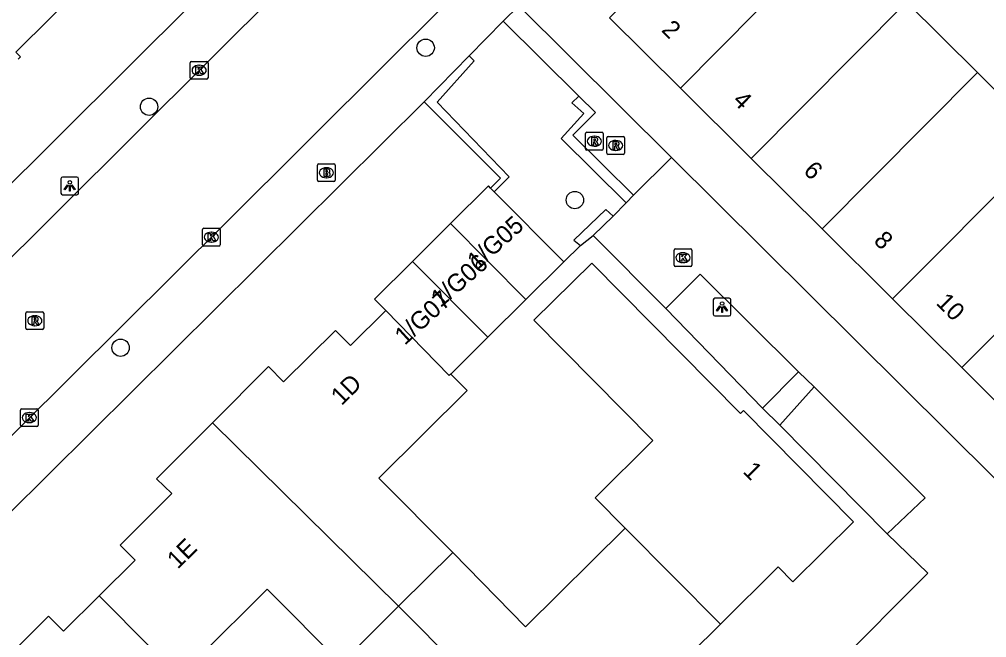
# Model space of a CAD drawing. Extents: x 159222 to 160346, y 381249 to 382166.
# Drawn here: x 160085.3 to 160139.8, y 381846.3 to 381881.1 of the extents above; entities that cross this region are included whole.
import ezdxf

# ---------------------------------------------------------------- set-up
doc = ezdxf.new("R2010")
doc.units = 0
for name, color, linetype in [('IMGEO_Boom', 7, 'Continuous'), ('IMGEO_Brandkraan', 7, 'Continuous'), ('IMGEO_Groenvoorziening', 7, 'Continuous'), ('IMGEO_Haag', 7, 'Continuous'), ('IMGEO_Kolk', 7, 'Continuous'), ('IMGEO_Lichtpunt', 7, 'Continuous'), ('IMGEO_Pand', 7, 'Continuous'), ('IMGEO_Pand_nummerreeks', 7, 'Continuous'), ('IMGEO_Rijbaan_lokaal_open', 7, 'Continuous'), ('IMGEO_Rioolput', 7, 'Continuous'), ('IMGEO_Voetpad_open', 7, 'Continuous')]:
    doc.layers.add(name, color=color, linetype=linetype)

msp = doc.modelspace()

# ---------------------------------------------------------------- linework, layer by layer
at = {"layer": 'IMGEO_Boom'}
for centre in [(160108.207, 381879.53), (160092.632, 381876.209), (160116.609, 381870.954), (160091.023, 381862.638)]:
    msp.add_circle(centre, 0.489, dxfattribs=at)
at = {"layer": 'IMGEO_Brandkraan'}
for p, q in [((160102.192, 381872.993), (160103.044, 381872.993)), ((160102.117, 381872.067), (160102.117, 381872.919)), ((160102.605, 381872.773), (160102.63, 381872.773)), ((160103.118, 381872.919), (160103.118, 381872.067)), ((160103.044, 381871.993), (160102.192, 381871.993)), ((160102.628, 381872.213), (160102.603, 381872.213))]:
    msp.add_line(p, q, dxfattribs=at)
for points in [[(160102.192, 381872.993), (160103.044, 381872.993)], [(160102.117, 381872.067), (160102.117, 381872.919)], [(160102.465, 381872.693), (160102.465, 381872.293), (160102.678, 381872.293)], [(160102.696, 381872.693), (160102.465, 381872.693)], [(160102.644, 381872.612), (160102.59, 381872.612), (160102.59, 381872.536)], [(160102.59, 381872.536), (160102.643, 381872.536)], [(160102.652, 381872.46), (160102.59, 381872.46), (160102.59, 381872.379)], [(160103.118, 381872.919), (160103.118, 381872.067)], [(160103.044, 381871.993), (160102.192, 381871.993)], [(160102.59, 381872.379), (160102.652, 381872.379)]]:
    msp.add_lwpolyline(points, dxfattribs=at)
for centre, radius, start, end in [((160102.194, 381872.917), 0.0765, 91.552, 178.448), ((160102.194, 381872.917), 0.0765, 91.552, 178.448), ((160103.042, 381872.917), 0.0765, 1.552, 88.448), ((160103.042, 381872.917), 0.0765, 1.552, 88.448), ((160102.645, 381872.574), 0.0379, 267.8285, 90.9355), ((160102.653, 381872.419), 0.0404, 269.8759, 90.5077), ((160102.7, 381872.548), 0.145, 59.4692, 91.5367), ((160102.725, 381872.595), 0.0922, 285.5137, 58.1501), ((160102.73, 381872.403), 0.105, 301.3115, 78.989), ((160102.194, 381872.069), 0.0765, 181.552, 268.448), ((160102.194, 381872.069), 0.0765, 181.552, 268.448), ((160102.684, 381872.544), 0.251, 268.6676, 293.5347), ((160103.042, 381872.069), 0.0765, 271.552, 358.448), ((160103.042, 381872.069), 0.0765, 271.552, 358.448)]:
    msp.add_arc(centre, radius, start, end, dxfattribs=at)
for centre, major_axis, ratio, start_param, end_param in [((160102.604, 381872.493), (-0.387, 0.002), 0.722429, 4.712389, 7.853982), ((160102.629, 381872.493), (-0.39, 0.002), 0.717154, 1.570796, 4.712389)]:
    msp.add_ellipse(centre, major_axis=major_axis, ratio=ratio, start_param=start_param, end_param=end_param, dxfattribs=at)
at = {"layer": 'IMGEO_Groenvoorziening'}
for points in [[(160115.983, 381867.48), (160116.932, 381868.397)], [(160127.18, 381859.24), (160121.731, 381864.845)], [(160134.193, 381852.151), (160128.145, 381858.27)]]:
    msp.add_lwpolyline(points, dxfattribs=at)
at = {"layer": 'IMGEO_Haag'}
for points in [[(160112.065, 381871.426), (160112.908, 381872.255), (160108.851, 381876.475), (160110.94, 381878.792), (160110.658, 381879.072)], [(160116.824, 381876.807), (160116.445, 381876.433), (160117.122, 381875.832), (160115.838, 381874.429), (160119.501, 381870.804)], [(160108.118, 381876.482), (160112.429, 381872.19), (160111.865, 381871.628)], [(160118.769, 381870.052), (160118.356, 381870.426), (160116.554, 381868.698), (160116.932, 381868.397)], [(160116.932, 381868.397), (160117.637, 381868.956)]]:
    msp.add_lwpolyline(points, dxfattribs=at)
at = {"layer": 'IMGEO_Kolk'}
for p, q in [((160094.948, 381877.838), (160094.948, 381878.69)), ((160095.023, 381878.764), (160095.875, 381878.764)), ((160095.436, 381878.544), (160095.461, 381878.544)), ((160095.949, 381878.69), (160095.949, 381877.838)), ((160095.459, 381877.984), (160095.434, 381877.984)), ((160095.875, 381877.764), (160095.023, 381877.764)), ((160095.64, 381868.439), (160095.64, 381869.291)), ((160095.715, 381869.365), (160096.567, 381869.365)), ((160096.641, 381869.291), (160096.641, 381868.439)), ((160096.128, 381869.145), (160096.153, 381869.145)), ((160096.567, 381868.365), (160095.715, 381868.365)), ((160096.151, 381868.585), (160096.126, 381868.585)), ((160122.194, 381867.283), (160122.194, 381868.135)), ((160122.269, 381868.209), (160123.121, 381868.209)), ((160123.195, 381868.135), (160123.195, 381867.283)), ((160122.682, 381867.989), (160122.707, 381867.989)), ((160123.121, 381867.209), (160122.269, 381867.209)), ((160122.705, 381867.429), (160122.68, 381867.429)), ((160085.387, 381858.277), (160085.387, 381859.129)), ((160085.462, 381859.203), (160086.314, 381859.203)), ((160085.875, 381858.983), (160085.9, 381858.983)), ((160086.388, 381859.129), (160086.388, 381858.277)), ((160085.898, 381858.423), (160085.873, 381858.423)), ((160086.314, 381858.203), (160085.462, 381858.203))]:
    msp.add_line(p, q, dxfattribs=at)
for points in [[(160094.948, 381877.838), (160094.948, 381878.69)], [(160095.023, 381878.764), (160095.875, 381878.764)], [(160095.269, 381878.464), (160095.392, 381878.464), (160095.392, 381878.313), (160095.522, 381878.464), (160095.686, 381878.464), (160095.54, 381878.313), (160095.693, 381878.064), (160095.541, 381878.064), (160095.456, 381878.228), (160095.392, 381878.161), (160095.392, 381878.064), (160095.269, 381878.064), (160095.269, 381878.464)], [(160095.949, 381878.69), (160095.949, 381877.838)], [(160095.875, 381877.764), (160095.023, 381877.764)], [(160095.64, 381868.439), (160095.64, 381869.291)], [(160095.715, 381869.365), (160096.567, 381869.365)], [(160096.641, 381869.291), (160096.641, 381868.439)], [(160095.961, 381869.065), (160096.084, 381869.065), (160096.084, 381868.914), (160096.214, 381869.065), (160096.378, 381869.065), (160096.232, 381868.914), (160096.385, 381868.665), (160096.233, 381868.665), (160096.148, 381868.829), (160096.084, 381868.762), (160096.084, 381868.665), (160095.961, 381868.665), (160095.961, 381869.065)], [(160096.567, 381868.365), (160095.715, 381868.365)], [(160122.194, 381867.283), (160122.194, 381868.135)], [(160122.269, 381868.209), (160123.121, 381868.209)], [(160123.195, 381868.135), (160123.195, 381867.283)], [(160122.515, 381867.909), (160122.638, 381867.909), (160122.638, 381867.758), (160122.768, 381867.909), (160122.932, 381867.909), (160122.786, 381867.758), (160122.939, 381867.509), (160122.787, 381867.509), (160122.702, 381867.673), (160122.638, 381867.606), (160122.638, 381867.509), (160122.515, 381867.509), (160122.515, 381867.909)], [(160123.121, 381867.209), (160122.269, 381867.209)], [(160085.387, 381858.277), (160085.387, 381859.129)], [(160085.462, 381859.203), (160086.314, 381859.203)], [(160085.708, 381858.903), (160085.831, 381858.903), (160085.831, 381858.752), (160085.961, 381858.903), (160086.125, 381858.903), (160085.979, 381858.752), (160086.132, 381858.503), (160085.98, 381858.503), (160085.895, 381858.667), (160085.831, 381858.6), (160085.831, 381858.503), (160085.708, 381858.503), (160085.708, 381858.903)], [(160086.388, 381859.129), (160086.388, 381858.277)], [(160086.314, 381858.203), (160085.462, 381858.203)]]:
    msp.add_lwpolyline(points, dxfattribs=at)
for centre, start, end in [((160095.025, 381878.688), 91.552, 178.448), ((160095.025, 381878.688), 91.552, 178.448), ((160095.873, 381878.688), 1.552, 88.448), ((160095.873, 381878.688), 1.552, 88.448), ((160095.025, 381877.84), 181.552, 268.448), ((160095.025, 381877.84), 181.552, 268.448), ((160095.873, 381877.84), 271.552, 358.448), ((160095.873, 381877.84), 271.552, 358.448), ((160095.717, 381869.289), 91.552, 178.448), ((160095.717, 381869.289), 91.552, 178.448), ((160096.565, 381869.289), 1.552, 88.448), ((160096.565, 381869.289), 1.552, 88.448), ((160095.717, 381868.441), 181.552, 268.448), ((160095.717, 381868.441), 181.552, 268.448), ((160096.565, 381868.441), 271.552, 358.448), ((160096.565, 381868.441), 271.552, 358.448), ((160122.271, 381868.133), 91.552, 178.448), ((160122.271, 381868.133), 91.552, 178.448), ((160123.119, 381868.133), 1.552, 88.448), ((160123.119, 381868.133), 1.552, 88.448), ((160122.271, 381867.285), 181.552, 268.448), ((160122.271, 381867.285), 181.552, 268.448), ((160123.119, 381867.285), 271.552, 358.448), ((160123.119, 381867.285), 271.552, 358.448), ((160085.464, 381859.127), 91.552, 178.448), ((160085.464, 381859.127), 91.552, 178.448), ((160086.312, 381859.127), 1.552, 88.448), ((160086.312, 381859.127), 1.552, 88.448), ((160085.464, 381858.279), 181.552, 268.448), ((160085.464, 381858.279), 181.552, 268.448), ((160086.312, 381858.279), 271.552, 358.448), ((160086.312, 381858.279), 271.552, 358.448)]:
    msp.add_arc(centre, 0.0765, start, end, dxfattribs=at)
for centre, major_axis, ratio, start_param, end_param in [((160095.435, 381878.264), (-0.387, 0.002), 0.722429, 4.712389, 7.853982), ((160095.46, 381878.264), (-0.39, 0.002), 0.717154, 1.570796, 4.712389), ((160096.127, 381868.865), (-0.387, 0.002), 0.722429, 4.712389, 7.853982), ((160096.152, 381868.865), (-0.39, 0.002), 0.717154, 1.570796, 4.712389), ((160122.681, 381867.709), (-0.387, 0.002), 0.722429, 4.712389, 7.853982), ((160122.706, 381867.709), (-0.39, 0.002), 0.717154, 1.570796, 4.712389), ((160085.874, 381858.703), (-0.387, 0.002), 0.722429, 4.712389, 7.853982), ((160085.899, 381858.703), (-0.39, 0.002), 0.717154, 1.570796, 4.712389)]:
    msp.add_ellipse(centre, major_axis=major_axis, ratio=ratio, start_param=start_param, end_param=end_param, dxfattribs=at)
at = {"layer": 'IMGEO_Lichtpunt'}
for p, q in [((160087.665, 381872.157), (160087.665, 381871.35)), ((160087.665, 381872.157), (160087.665, 381871.35)), ((160088.567, 381872.252), (160087.759, 381872.252)), ((160088.567, 381872.252), (160087.759, 381872.252)), ((160088.661, 381871.35), (160088.661, 381872.157)), ((160088.661, 381871.35), (160088.661, 381872.157)), ((160087.759, 381871.256), (160088.567, 381871.256)), ((160087.759, 381871.256), (160088.567, 381871.256)), ((160125.304, 381865.423), (160124.496, 381865.423)), ((160125.304, 381865.423), (160124.496, 381865.423)), ((160124.402, 381865.328), (160124.402, 381864.521)), ((160124.402, 381865.328), (160124.402, 381864.521)), ((160125.398, 381864.521), (160125.398, 381865.328)), ((160125.398, 381864.521), (160125.398, 381865.328)), ((160124.496, 381864.427), (160125.304, 381864.427)), ((160124.496, 381864.427), (160125.304, 381864.427))]:
    msp.add_line(p, q, dxfattribs=at)
for points in [[(160088.039, 381871.821), (160088.078, 381871.793), (160087.89, 381871.531), (160087.852, 381871.558), (160088.039, 381871.821)], [(160088.141, 381871.773), (160088.188, 381871.773), (160088.188, 381871.451), (160088.141, 381871.451), (160088.141, 381871.773)], [(160088.251, 381871.793), (160088.289, 381871.82), (160088.476, 381871.558), (160088.437, 381871.53), (160088.251, 381871.793)], [(160124.776, 381864.992), (160124.815, 381864.964), (160124.627, 381864.702), (160124.589, 381864.729), (160124.776, 381864.992)], [(160124.878, 381864.944), (160124.925, 381864.944), (160124.925, 381864.622), (160124.878, 381864.622), (160124.878, 381864.944)], [(160124.988, 381864.964), (160125.026, 381864.991), (160125.213, 381864.729), (160125.174, 381864.701), (160124.988, 381864.964)]]:
    msp.add_lwpolyline(points, dxfattribs=at)
for centre in [(160088.164, 381871.955), (160124.901, 381865.126)]:
    msp.add_circle(centre, 0.0994, dxfattribs=at)
for centre, start, end in [((160087.759, 381872.157), 90, 180), ((160087.759, 381872.157), 90, 180), ((160088.567, 381872.157), 0, 90), ((160088.567, 381872.157), 0, 90), ((160087.759, 381871.35), 180, 270), ((160087.759, 381871.35), 180, 270), ((160088.567, 381871.35), 270, 0), ((160088.567, 381871.35), 270, 360), ((160124.496, 381865.328), 90, 180), ((160124.496, 381865.328), 90, 180), ((160125.304, 381865.328), 0, 90), ((160125.304, 381865.328), 0, 90), ((160124.496, 381864.521), 180, 270), ((160124.496, 381864.521), 180, 270), ((160125.304, 381864.521), 270, 0), ((160125.304, 381864.521), 270, 360)]:
    msp.add_arc(centre, 0.0946, start, end, dxfattribs=at)
at = {"layer": 'IMGEO_Pand'}
for points in [[(160131.293, 381886.07), (160127.297, 381890.032), (160124.926, 381887.639), (160124.286, 381888.273), (160122.15, 381886.117), (160122.789, 381885.483), (160118.566, 381881.222), (160122.556, 381877.258)], [(160122.556, 381877.258), (160131.293, 381886.07)], [(160089.462, 381883.13), (160089.361, 381883.029), (160089.133, 381883.258), (160085.132, 381879.279), (160085.388, 381879.022), (160085.261, 381878.896)], [(160135.289, 381882.107), (160126.548, 381873.292)], [(160139.285, 381878.145), (160135.289, 381882.107)], [(160139.285, 381878.145), (160130.54, 381869.325)], [(160142.426, 381873.326), (160143.281, 381874.182), (160139.285, 381878.145)], [(160122.556, 381877.258), (160126.548, 381873.292)], [(160126.548, 381873.292), (160130.54, 381869.325)], [(160134.5, 381865.391), (160142.426, 381873.326)], [(160111.865, 381871.628), (160111.742, 381871.752), (160109.602, 381869.627)], [(160111.865, 381871.628), (160112.065, 381871.426)], [(160112.065, 381871.426), (160115.983, 381867.48)], [(160107.461, 381867.501), (160109.602, 381869.627)], [(160109.602, 381869.627), (160113.843, 381865.355)], [(160130.54, 381869.325), (160134.5, 381865.391)], [(160145.46, 381868.584), (160138.4, 381861.516)], [(160105.956, 381864.738), (160105.321, 381865.376), (160107.461, 381867.501)], [(160107.461, 381867.501), (160111.703, 381863.23)], [(160113.843, 381865.355), (160115.983, 381867.48)], [(160119.451, 381852.482), (160117.758, 381854.194), (160121.007, 381857.41), (160114.305, 381864.183), (160117.565, 381867.408), (160125.939, 381858.944), (160126.11, 381859.108), (160132.303, 381852.828), (160128.883, 381849.455), (160128.067, 381850.297), (160124.804, 381847.069)], [(160113.843, 381865.355), (160111.703, 381863.23)], [(160134.5, 381865.391), (160138.4, 381861.516)], [(160096.203, 381858.406), (160099.364, 381861.575), (160100.209, 381860.723), (160103.125, 381863.618), (160103.97, 381862.766), (160105.956, 381864.738)], [(160109.617, 381861.159), (160109.54, 381861.082), (160105.956, 381864.738)], [(160111.703, 381863.23), (160109.617, 381861.159)], [(160109.617, 381861.159), (160110.54, 381860.229), (160105.572, 381855.296), (160109.729, 381851.109)], [(160138.4, 381861.516), (160141.958, 381857.981)], [(160089.817, 381848.663), (160091.84, 381850.673), (160090.995, 381851.525), (160093.911, 381854.422), (160093.057, 381855.252), (160096.203, 381858.406)], [(160106.684, 381848.086), (160096.203, 381858.406)], [(160109.729, 381851.109), (160113.833, 381846.923), (160119.451, 381852.482)], [(160119.451, 381852.482), (160124.804, 381847.069)], [(160109.729, 381851.109), (160106.756, 381848.157), (160106.684, 381848.086)], [(160103.442, 381844.852), (160099.281, 381849.042), (160095.429, 381845.217), (160096.721, 381843.916), (160095.626, 381842.828)], [(160080.044, 381842.336), (160083.216, 381845.488), (160084.062, 381844.637), (160086.971, 381847.527), (160087.817, 381846.676), (160089.817, 381848.663)], [(160095.626, 381842.828), (160089.817, 381848.663)], [(160106.684, 381848.086), (160103.442, 381844.852)], [(160106.684, 381848.086), (160113.509, 381841.213), (160117.032, 381837.665)], [(160124.804, 381847.069), (160119.718, 381842.038), (160120.561, 381841.185), (160117.032, 381837.665)]]:
    msp.add_lwpolyline(points, dxfattribs=at)
at = {"layer": 'IMGEO_Rijbaan_lokaal_open'}
for points in [[(160002.99, 381786.2), (160012.11, 381795.292), (160116.933, 381899.648), (160120.802, 381903.57), (160121.409, 381904.226), (160123.621, 381906.761), (160125.502, 381909.146), (160137.982, 381924.966), (160137.985, 381924.969)], [(160116.227, 381888.855), (160106.101, 381878.782), (160096.927, 381869.656), (160085.354, 381858.143), (160080.535, 381853.35), (160070.584, 381843.451), (160069.21, 381842.087), (160064.536, 381837.45), (160052.791, 381825.786), (160048.168, 381821.179), (160036.822, 381809.873), (160032.195, 381805.263), (160022.766, 381795.885), (160020.046, 381793.267), (160016.183, 381789.42), (160010.858, 381784.097), (160007.94, 381781.256)], [(160119.917, 381871.221), (160122.049, 381873.351)], [(160122.049, 381873.351), (160145.414, 381850.161)], [(160118.769, 381870.052), (160119.501, 381870.804)], [(160119.501, 381870.804), (160119.917, 381871.221)], [(160117.637, 381868.956), (160118.769, 381870.052)], [(160121.731, 381864.845), (160117.637, 381868.956)], [(160129.196, 381861.275), (160123.668, 381866.777), (160121.731, 381864.845)], [(160130.087, 381860.444), (160129.196, 381861.275)], [(160134.193, 381852.151), (160136.344, 381854.192), (160130.087, 381860.444)], [(160120.656, 381834.07), (160136.491, 381849.949), (160134.193, 381852.151)]]:
    msp.add_lwpolyline(points, dxfattribs=at)
at = {"layer": 'IMGEO_Rioolput'}
for p, q in [((160117.209, 381873.843), (160117.209, 381874.695)), ((160117.284, 381874.769), (160118.136, 381874.769)), ((160118.21, 381874.695), (160118.21, 381873.843)), ((160117.697, 381874.549), (160117.722, 381874.549)), ((160118.409, 381873.603), (160118.409, 381874.455)), ((160118.484, 381874.529), (160119.336, 381874.529)), ((160118.897, 381874.309), (160118.922, 381874.309)), ((160119.41, 381874.455), (160119.41, 381873.603)), ((160118.136, 381873.769), (160117.284, 381873.769)), ((160117.72, 381873.989), (160117.695, 381873.989)), ((160119.336, 381873.529), (160118.484, 381873.529)), ((160118.92, 381873.749), (160118.895, 381873.749)), ((160085.693, 381863.734), (160085.693, 381864.586)), ((160085.768, 381864.66), (160086.62, 381864.66)), ((160086.181, 381864.44), (160086.206, 381864.44)), ((160086.694, 381864.586), (160086.694, 381863.734)), ((160086.204, 381863.88), (160086.179, 381863.88)), ((160086.62, 381863.66), (160085.768, 381863.66))]:
    msp.add_line(p, q, dxfattribs=at)
for points in [[(160117.209, 381873.843), (160117.209, 381874.695)], [(160117.284, 381874.769), (160118.136, 381874.769)], [(160118.21, 381874.695), (160118.21, 381873.843)], [(160117.798, 381874.467), (160117.546, 381874.469), (160117.546, 381874.069)], [(160117.546, 381874.069), (160117.67, 381874.069), (160117.67, 381874.231), (160117.681, 381874.231)], [(160117.724, 381874.388), (160117.67, 381874.388), (160117.67, 381874.307)], [(160117.67, 381874.307), (160117.722, 381874.307)], [(160117.728, 381874.202), (160117.799, 381874.069), (160117.939, 381874.069), (160117.874, 381874.195)], [(160118.409, 381873.603), (160118.409, 381874.455)], [(160118.484, 381874.529), (160119.336, 381874.529)], [(160118.998, 381874.227), (160118.746, 381874.229), (160118.746, 381873.829)], [(160118.924, 381874.148), (160118.87, 381874.148), (160118.87, 381874.067)], [(160118.87, 381874.067), (160118.922, 381874.067)], [(160119.41, 381874.455), (160119.41, 381873.603)], [(160118.136, 381873.769), (160117.284, 381873.769)], [(160119.336, 381873.529), (160118.484, 381873.529)], [(160118.746, 381873.829), (160118.87, 381873.829), (160118.87, 381873.991), (160118.881, 381873.991)], [(160118.928, 381873.962), (160118.999, 381873.829), (160119.139, 381873.829), (160119.074, 381873.955)], [(160085.693, 381863.734), (160085.693, 381864.586)], [(160085.768, 381864.66), (160086.62, 381864.66)], [(160086.282, 381864.358), (160086.03, 381864.36), (160086.03, 381863.96)], [(160086.208, 381864.279), (160086.154, 381864.279), (160086.154, 381864.198)], [(160086.694, 381864.586), (160086.694, 381863.734)], [(160086.03, 381863.96), (160086.154, 381863.96), (160086.154, 381864.122), (160086.165, 381864.122)], [(160086.154, 381864.198), (160086.206, 381864.198)], [(160086.212, 381864.093), (160086.283, 381863.96), (160086.423, 381863.96), (160086.358, 381864.086)], [(160086.62, 381863.66), (160085.768, 381863.66)]]:
    msp.add_lwpolyline(points, dxfattribs=at)
for centre, radius, start, end in [((160117.286, 381874.693), 0.0765, 91.552, 178.448), ((160117.286, 381874.693), 0.0765, 91.552, 178.448), ((160118.134, 381874.693), 0.0765, 1.552, 88.448), ((160118.134, 381874.693), 0.0765, 1.552, 88.448), ((160117.68, 381874.178), 0.0533, 26.0293, 88.6989), ((160117.706, 381874.496), 0.19, 274.7715, 282.9687), ((160117.73, 381874.292), 0.0964, 77.0061, 93.1865), ((160117.744, 381874.349), 0.0378, 276.6634, 79.6772), ((160117.797, 381874.357), 0.109, 350.3612, 89.416), ((160117.795, 381874.357), 0.112, 277.5842, 350.9817), ((160117.779, 381874.142), 0.108, 29.5134, 73.7905), ((160118.486, 381874.453), 0.0765, 91.552, 178.448), ((160118.486, 381874.453), 0.0765, 91.552, 178.448), ((160118.906, 381874.256), 0.19, 274.7715, 282.9687), ((160118.93, 381874.052), 0.0964, 77.0061, 93.1865), ((160118.944, 381874.109), 0.0378, 276.6634, 79.6772), ((160118.997, 381874.117), 0.109, 350.3612, 89.416), ((160118.995, 381874.117), 0.112, 277.5842, 350.9817), ((160119.334, 381874.453), 0.0765, 1.552, 88.448), ((160119.334, 381874.453), 0.0765, 1.552, 88.448), ((160117.286, 381873.845), 0.0765, 181.552, 268.448), ((160117.286, 381873.845), 0.0765, 181.552, 268.448), ((160118.134, 381873.845), 0.0765, 271.552, 358.448), ((160118.134, 381873.845), 0.0765, 271.552, 358.448), ((160118.486, 381873.605), 0.0765, 181.552, 268.448), ((160118.486, 381873.605), 0.0765, 181.552, 268.448), ((160118.88, 381873.938), 0.0533, 26.0293, 88.6989), ((160118.979, 381873.902), 0.108, 29.5134, 73.7905), ((160119.334, 381873.605), 0.0765, 271.552, 358.448), ((160119.334, 381873.605), 0.0765, 271.552, 358.448), ((160085.77, 381864.584), 0.0765, 91.552, 178.448), ((160085.77, 381864.584), 0.0765, 91.552, 178.448), ((160086.214, 381864.183), 0.0964, 77.0061, 93.1865), ((160086.228, 381864.24), 0.0378, 276.6634, 79.6772), ((160086.281, 381864.248), 0.109, 350.3612, 89.416), ((160086.618, 381864.584), 0.0765, 1.552, 88.448), ((160086.618, 381864.584), 0.0765, 1.552, 88.448), ((160085.77, 381863.736), 0.0765, 181.552, 268.448), ((160085.77, 381863.736), 0.0765, 181.552, 268.448), ((160086.164, 381864.069), 0.0533, 26.0293, 88.6989), ((160086.19, 381864.387), 0.19, 274.7715, 282.9687), ((160086.279, 381864.248), 0.112, 277.5842, 350.9817), ((160086.263, 381864.033), 0.108, 29.5134, 73.7905), ((160086.618, 381863.736), 0.0765, 271.552, 358.448), ((160086.618, 381863.736), 0.0765, 271.552, 358.448)]:
    msp.add_arc(centre, radius, start, end, dxfattribs=at)
for centre, major_axis, ratio, start_param, end_param in [((160117.696, 381874.269), (-0.387, 0.002), 0.722429, 4.712389, 7.853982), ((160117.721, 381874.269), (-0.39, 0.002), 0.717154, 1.570796, 4.712389), ((160118.896, 381874.029), (-0.387, 0.002), 0.722429, 4.712389, 7.853982), ((160118.921, 381874.029), (-0.39, 0.002), 0.717154, 1.570796, 4.712389), ((160086.18, 381864.16), (-0.387, 0.002), 0.722429, 4.712389, 7.853982), ((160086.205, 381864.16), (-0.39, 0.002), 0.717154, 1.570796, 4.712389)]:
    msp.add_ellipse(centre, major_axis=major_axis, ratio=ratio, start_param=start_param, end_param=end_param, dxfattribs=at)
at = {"layer": 'IMGEO_Voetpad_open'}
for points in [[(160079.939, 381867.002), (160114.243, 381901.129), (160118.056, 381905.241)], [(160112.581, 381881.023), (160113.448, 381881.888)], [(160113.448, 381881.888), (160122.049, 381873.351)], [(160112.581, 381881.023), (160110.658, 381879.072)], [(160116.824, 381876.807), (160112.581, 381881.023)], [(160110.658, 381879.072), (160108.118, 381876.482)], [(160119.917, 381871.221), (160116.496, 381874.602), (160117.768, 381875.885), (160116.824, 381876.807)], [(160108.118, 381876.482), (160028.327, 381797.338), (160012.912, 381781.871), (160008.385, 381777.496)], [(160129.196, 381861.275), (160127.18, 381859.24)], [(160128.145, 381858.27), (160130.087, 381860.444)], [(160127.18, 381859.24), (160128.145, 381858.27)]]:
    msp.add_lwpolyline(points, dxfattribs=at)

# ---------------------------------------------------------------- texts
at = {"layer": 'IMGEO_Pand_nummerreeks'}
for s, rotation, p in [('2', 315.1832, (160121.434, 381880.486)), ('4', 315.1832, (160125.444, 381876.502)), ('6', 315.1832, (160129.429, 381872.543)), ('1/G05', 42.0379, (160111.104, 381866.968)), ('8', 315.1832, (160133.388, 381868.61)), ('1/G06', 40.8888, (160109.043, 381864.865)), ('1/G07', 42.3523, (160107.026, 381862.74)), ('10', 315.1832, (160136.9, 381865.121)), ('1D', 44.7929, (160103.472, 381859.339)), ('1', 314.5988, (160126.028, 381855.63)), ('1E', 44.8127, (160094.244, 381850.128))]:
    msp.add_text(s, height=1, rotation=rotation, dxfattribs=at).set_placement(p)

doc.saveas('drawing.dxf')
